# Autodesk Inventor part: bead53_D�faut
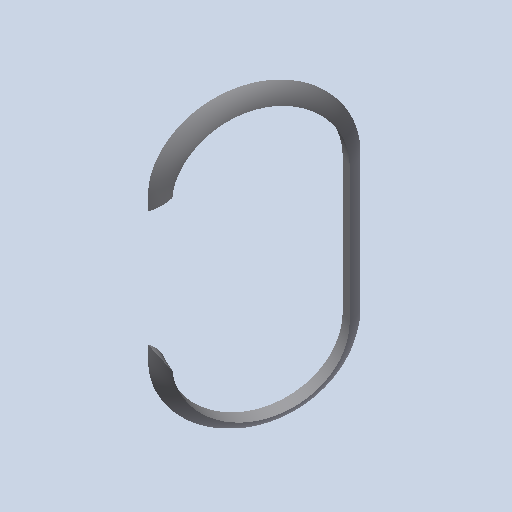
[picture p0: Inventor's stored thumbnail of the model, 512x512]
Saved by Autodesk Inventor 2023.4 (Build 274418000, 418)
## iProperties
Created: 2011-01
Part Number: bead53_D�faut
Document SubType Name: Modeling
Designer: eric
Density: 1 g/cm^3
Mass: 0.213539 g
Surface Area: 6.08546 cm^2
Volume: 0.213539 cm^3
Material: Générique
Appearance: Par défaut
Author: eric
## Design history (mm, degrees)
feature "Base1"
node "Corps solides"
node "Corps surfaciques"
node "Solide1"
